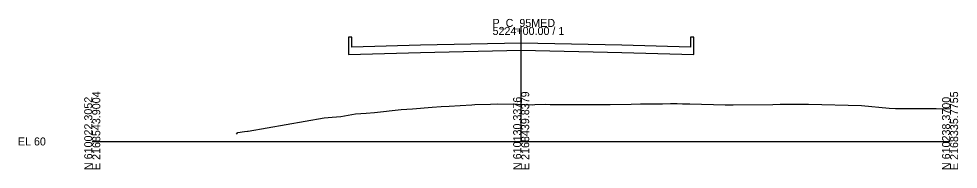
# Model space of a CAD drawing. Extents: x -26 to 303, y -10 to 10517.
# Drawn here: x -25.7 to 302.8, y 3990.3 to 4042.8 of the extents above; entities that cross this region are included whole.
import ezdxf

# ---------------------------------------------------------------- set-up
doc = ezdxf.new("R2010")
doc.units = 0
for name, color, linetype in [('RD_GPK_XS_Cell', 7, 'Continuous'), ('RD_PD_Final_TrvlWay', 7, 'Continuous'), ('RD_XS_ExGround', 7, 'Continuous')]:
    doc.layers.add(name, color=color, linetype=linetype)

msp = doc.modelspace()

# ---------------------------------------------------------------- linework, layer by layer
at = {"layer": 'RD_GPK_XS_Cell'}
for p, q in [((150, 4000), (150, 4040)), ((0, 4000), (150, 4000)), ((150, 4000), (300, 4000))]:
    msp.add_line(p, q, dxfattribs=at)
at = {"layer": 'RD_PD_Final_TrvlWay'}
for p, q in [((90.75, 4036.41), (89.62, 4036.41)), ((89.62, 4036.41), (89.62, 4036.41)), ((89.62, 4036.41), (89.62, 4030.32)), ((90.83, 4032.91), (90.75, 4036.41)), ((90.75, 4036.41), (90.75, 4036.41)), ((90.75, 4036.41), (90.75, 4036.41)), ((150, 4034.39), (114.83, 4033.69)), ((185.17, 4033.69), (150, 4034.39)), ((150, 4034.39), (150, 4034.39)), ((150, 4034.39), (150, 4034.39)), ((209.25, 4036.41), (209.17, 4032.91)), ((210.38, 4036.41), (209.25, 4036.41)), ((209.25, 4036.41), (209.25, 4036.41)), ((209.25, 4036.41), (209.25, 4036.41)), ((210.38, 4030.32), (210.38, 4036.41)), ((210.38, 4036.41), (210.38, 4036.41)), ((89.62, 4030.32), (114.83, 4031.13)), ((114.83, 4033.69), (90.83, 4032.91)), ((114.83, 4033.69), (114.83, 4033.69)), ((114.83, 4031.13), (150, 4031.83)), ((114.83, 4031.13), (114.83, 4031.13)), ((150, 4031.83), (150, 4031.83)), ((150, 4031.83), (150, 4031.83)), ((150, 4031.83), (185.17, 4031.13)), ((209.17, 4032.91), (185.17, 4033.69)), ((185.17, 4033.69), (185.17, 4033.69)), ((185.17, 4031.13), (185.17, 4031.13)), ((185.17, 4031.13), (210.38, 4030.32))]:
    msp.add_line(p, q, dxfattribs=at)
at = {"layer": 'RD_XS_ExGround'}
msp.add_lwpolyline([(50.39, 4002.51), (50.86, 4003.18), (53.28, 4003.45), (54.27, 4003.55), (54.29, 4003.56), (54.46, 4003.59), (54.49, 4003.6), (54.51, 4003.6), (54.54, 4003.6), (81.16, 4008.21), (83.92, 4008.47), (86.97, 4008.76), (92.04, 4009.64), (95.77, 4009.92), (98.69, 4010.16), (107.99, 4011.11), (111.94, 4011.45), (118.91, 4011.92), (122.06, 4012.16), (124.84, 4012.38), (128.72, 4012.59), (132.78, 4012.81), (133.81, 4012.85), (139.27, 4013.04), (141.81, 4013.12), (148.74, 4012.98), (154.04, 4012.84), (154.82, 4012.88), (158.42, 4012.98), (160.1, 4012.95), (164.17, 4012.89), (168.01, 4012.87), (173.69, 4012.89), (176.89, 4012.92), (181.14, 4012.96), (188.45, 4013.02), (191.75, 4013.1), (191.86, 4013.1), (194.48, 4013.12), (196.15, 4013.13), (199.44, 4013.18), (202.28, 4013.23), (204.55, 4013.23), (206.46, 4013.17), (208.98, 4013.09), (221.3, 4012.81), (222.95, 4012.81), (224.1, 4012.79), (237.97, 4012.95), (240.6, 4012.97), (247.42, 4012.99), (249.97, 4012.97), (250.5, 4012.98), (269.02, 4012.53), (278.7, 4011.59), (280.96, 4011.55), (287.15, 4011.52), (292.39, 4011.5), (292.44, 4011.5), (294.73, 4011.49), (295.14, 4011.48), (300, 4011.42)], dxfattribs=at)

# ---------------------------------------------------------------- texts
at = {"layer": 'RD_GPK_XS_Cell'}
for s, p in [('P_C_95MED', (140, 4040)), ('5224+00.00 / 1', (140, 4037.2)), ('EL 60', (-26, 3998.6))]:
    msp.add_text(s, height=2.8, dxfattribs=at).set_placement(p)
for s, p in [('N 610022.3052', (0, 3990)), ('E 2168543.9004', (2.8, 3990)), ('N 610130.3376', (150, 3990)), ('E 2168439.8379', (152.8, 3990)), ('N 610238.3700', (300, 3990)), ('E 2168335.7755', (302.8, 3990))]:
    msp.add_text(s, height=2.8, rotation=90, dxfattribs=at).set_placement(p)

doc.saveas('drawing.dxf')
